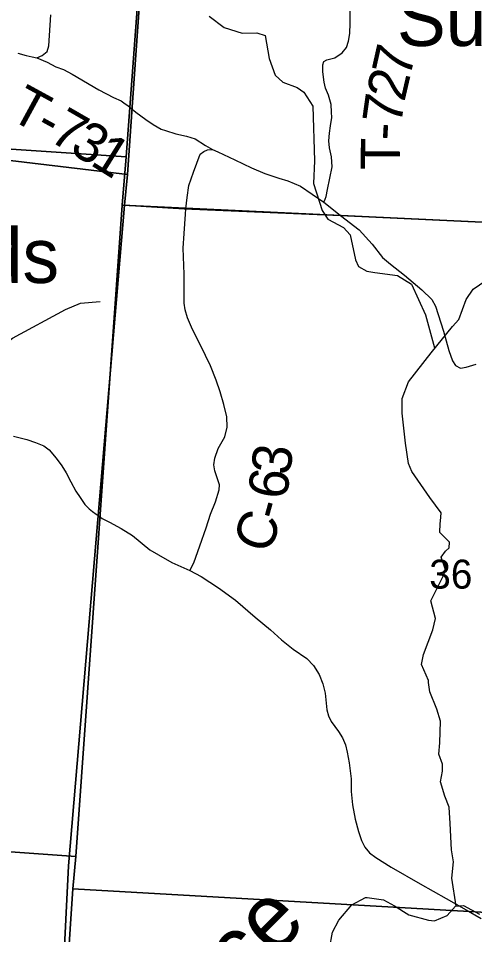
# Model space of a CAD drawing. Extents: x 1878108 to 2183446, y 146837 to 508383.
# Drawn here: x 2015902 to 2019382, y 336667 to 343657 of the extents above; entities that cross this region are included whole.
import ezdxf

# ---------------------------------------------------------------- set-up
doc = ezdxf.new("R2010")
doc.units = 0
for name, color, linetype in [('GM_X_County_Road', 7, 'Continuous'), ('GM_X_County_Road_Text', 7, 'Continuous'), ('GM_X_Minor_River', 7, 'Continuous'), ('GM_X_Minor_River_Text', 7, 'Continuous'), ('GM_X_Section', 7, 'Continuous'), ('GM_X_Section_Text', 7, 'Continuous'), ('GM_X_Township', 7, 'Continuous'), ('GM_X_Township_Road', 7, 'Continuous'), ('GM_X_Township_Road_Text', 7, 'Continuous'), ('GM_X_Unincorporated_Text', 7, 'Continuous')]:
    doc.layers.add(name, color=color, linetype=linetype)

msp = doc.modelspace()

# ---------------------------------------------------------------- linework, layer by layer
at = {"layer": 'GM_X_County_Road'}
for points in [[(2015898.6, 343392.5), (2015962.6, 343374.5), (2016007.5, 343363.3), (2016044.3, 343357), (2016083.9, 343374.5), (2016120.9, 343404.8), (2016135.5, 343447.5), (2016149, 343684.4)], [(2017177, 342162.8), (2017179.9, 342203.8), (2017190.4, 342290.2), (2017202.1, 342381.1), (2017237.3, 342483.8), (2017288.1, 342620.6), (2017316.4, 342642.1), (2017344.8, 342654.8), (2017383.9, 342655.8), (2017423, 342639.1), (2017552.9, 342576.6), (2017680, 342516), (2017782.6, 342474), (2017888.2, 342437.8), (2017956.6, 342418.3), (2018053.8, 342376.3), (2018231.1, 342253.6), (2018355.4, 342154.9)], [(2017210.9, 339445.2), (2017239.2, 339503.9), (2017285.2, 339632), (2017334, 339769.8), (2017368.2, 339874.3), (2017406.4, 339968.2), (2017433.7, 340059.1), (2017435.7, 340098.1), (2017423.9, 340136.3), (2017399.5, 340205.7), (2017393.6, 340250.6), (2017400.5, 340302.4), (2017426.9, 340375.7), (2017475.7, 340465.6), (2017493.3, 340537.9), (2017492.4, 340616.1), (2017469.9, 340711.9), (2017440.6, 340807.7), (2017410.3, 340895.6), (2017366.3, 341005.1), (2017329.1, 341086.2), (2017287.1, 341173.2), (2017231.4, 341283.6), (2017191.3, 341373.5), (2017174.7, 341432.2), (2017165.9, 341484), (2017166.9, 341596.4), (2017165.9, 341704.8), (2017158.1, 341903.2), (2017166.9, 342014.6), (2017177, 342162.8)], [(2018355.4, 342154.9), (2018357.7, 342153.1), (2018501, 342044.8), (2018600.4, 341934.3), (2018678, 341832), (2018739.2, 341782.6), (2018847.8, 341698), (2018979, 341585.1), (2019054.2, 341512.2), (2019083.6, 341461.7), (2019144.7, 341271.2), (2019185.9, 341123.1), (2019211.7, 341044.4), (2019235.2, 341009.1), (2019272.9, 340987.9), (2019316.3, 340995), (2019393.9, 341018.5)], [(2015866, 340470.3), (2015968, 340443.2), (2016032.5, 340421.3), (2016095.7, 340395.5), (2016138.3, 340365.8), (2016189.9, 340301.3), (2016235.1, 340243.2), (2016267.3, 340190.3), (2016302.2, 340120.6), (2016339.6, 340049.7), (2016374.4, 340000.6), (2016410.5, 339947.7), (2016442.8, 339915.5), (2016467.3, 339894.8), (2016496.6, 339874.8)], [(2016496.6, 339874.8), (2016510.3, 339865.4), (2016542.2, 339841.9), (2016596.4, 339812.3), (2016686.7, 339765.8), (2016771.8, 339711.6), (2016906, 339603.2), (2016970.5, 339563.2), (2017073.8, 339506.5), (2017210.9, 339445.2)], [(2017210.9, 339445.2), (2017295.7, 339399.4), (2017427.3, 339311.6), (2017558.9, 339217.4), (2017708.6, 339089.7), (2017824.7, 338991.6), (2017909.9, 338916.8), (2017998.9, 338845.8), (2018100.9, 338772.3), (2018153.8, 338720.7), (2018196.3, 338652.3), (2018223.4, 338580), (2018241.5, 338509), (2018255.7, 338382.6), (2018266, 338336.1), (2018286.7, 338293.6), (2018343.4, 338216.1), (2018374.4, 338167.1), (2018396.3, 338115.5), (2018410.5, 338060), (2018424.7, 337977.4), (2018438.9, 337856.1), (2018438.9, 337759.4), (2018450.5, 337656.1), (2018469.9, 337549), (2018497, 337453.6), (2018517.6, 337383.9), (2018543.4, 337333.6), (2018580.9, 337289.7), (2018628.6, 337254.9), (2018744.7, 337181.3), (2018966.7, 337053.6), (2019164.1, 336942.6), (2019317.6, 336854.9), (2019432.5, 336789.1)]]:
    msp.add_lwpolyline(points, dxfattribs=at)
at = {"layer": 'GM_X_Minor_River'}
for points in [[(2017358.5, 343674.5), (2017472.9, 343588.5), (2017609.2, 343544.7), (2017721.3, 343547), (2017783.5, 343527.1), (2017815.9, 343350.6), (2017860.2, 343222.4), (2017918.4, 343170.4), (2018028.7, 343128.5), (2018078.8, 343094.5), (2018147.2, 342986.4), (2018160.1, 342571.2), (2018152.5, 342396.7), (2018219, 342192.3), (2018263.3, 342126.2), (2018381.6, 342060.3), (2018431.8, 342006.2), (2018472.3, 341813.8), (2018496.4, 341763.7), (2018560.6, 341727.7), (2018620.7, 341717.9), (2018793, 341694.2), (2018901.3, 341630.3), (2019006, 341395.9), (2019076.4, 341142.8)], [(2019241.4, 336884.6), (2019208.2, 337096.7), (2019220.1, 337223), (2019206, 337313.3), (2019195.9, 337515.8), (2019187.8, 337640.2), (2019153.7, 337724.3), (2019121.6, 337832.6), (2019135.5, 337912.8), (2019135.5, 337967), (2019109.4, 338043.2), (2019115.4, 338129.4), (2019121.2, 338295.9), (2019093.2, 338386.1), (2019041.1, 338520.4), (2019031, 338590.6), (2019029, 338606.6), (2018976.9, 338726.8), (2018992.8, 338805.1), (2019062.6, 338991.7), (2019082.6, 339078), (2019046.5, 339214.3), (2019142.3, 339401), (2019158.2, 339451.1), (2019126.1, 339547.4), (2019160.1, 339593.5), (2019186.1, 339617.7), (2019190, 339661.8), (2019116, 339733.9), (2019117.9, 339804), (2019121.9, 339820.1), (2019125.9, 339884.3), (2019039.8, 340000.5), (2018903.7, 340200.8), (2018877.6, 340260.9), (2018853.5, 340415.3), (2018829.3, 340645.9), (2018829.2, 340758.2), (2018877.1, 340884.6), (2019050.8, 341105.5), (2019212.6, 341306.3), (2019260.5, 341360.5), (2019316.4, 341511), (2019370.3, 341591.3), (2019570.1, 341728.1)], [(2015247.7, 340749.3), (2015361.5, 340904.9), (2015427.4, 340955.1), (2015539.3, 340991.3), (2015659, 341067.6), (2015858.7, 341216.1), (2016262, 341435.1), (2016375.8, 341483.4), (2016525.6, 341495.7)], [(2018275.1, 336557.6), (2018297, 336686), (2018344.9, 336778.3), (2018444.7, 336894.8), (2018548.6, 336951.2), (2018562.6, 336951.2), (2018686.6, 336931.3), (2018770.6, 336887.4), (2018880.6, 336817.3), (2019030.6, 336777.5), (2019076.5, 336771.5), (2019172.5, 336811.8), (2019234.4, 336884.1), (2019296.4, 336888.2), (2019418.4, 336822.2)]]:
    msp.add_lwpolyline(points, dxfattribs=at)
at = {"layer": 'GM_X_Section'}
for points in [[(2017121.1, 347933.9), (2017107.5, 347769.8), (2016724.2, 342600), (2011392.3, 342956.8), (2011214.3, 342968.4), (2011587.2, 348298.2)], [(2022491.3, 347433.1), (2022076.7, 341977.1), (2016695, 342231.8), (2016724.2, 342600), (2017107.5, 347769.8)], [(2011392.3, 342956.8), (2016724.2, 342600), (2016695, 342231.8), (2016339.4, 337264), (2011013.4, 337644.9)], [(2016695, 342231.8), (2022076.7, 341977.1), (2021741.7, 336707.3), (2016317.9, 337015.9), (2016339.4, 337264)], [(2016339.4, 337264), (2016317.9, 337015.9), (2015982.4, 331960.2), (2010634.5, 332291), (2011013.4, 337644.9)], [(2021741.7, 336707.3), (2021372.8, 331397.4), (2015958.9, 331706.1), (2015982.4, 331960.2), (2016317.9, 337015.9)]]:
    msp.add_lwpolyline(points, close=True, dxfattribs=at)
at = {"layer": 'GM_X_Township'}
for points in [[(2022085.4, 341976.5), (2018357.7, 342153.1), (2017167.6, 342204.4), (2016711.2, 342233), (2016735.7, 342465.3), (2016771.3, 342980.5), (2016876.3, 344500.5), (2017298, 350114.1), (2017363.4, 350984.7), (2017639.3, 354834.1), (2017696.9, 355615), (2017915.9, 358580.9), (2018284.3, 364566.1), (2018295.1, 364714.1), (2018544, 369044.3), (2019393.9, 369074.7)], [(2017298, 350114.1), (2016876.3, 344500.5), (2016771.3, 342980.5), (2016735.7, 342465.3), (2014090.7, 342780.8), (2012240.2, 342898.1), (2008693, 343157.7), (2004354.1, 343457.5), (2003141.6, 343548.2), (2000896.9, 343716.1), (1999693.4, 343807.9), (1997660.6, 343962.9), (1995715.1, 344111.2), (1994970.8, 344177.4), (1990310.6, 344542.4), (1989690.7, 344598.5), (1988327.1, 344706.4), (1984472.4, 345011.3), (1984423, 345015.2), (1984436.4, 345172.5), (1984507.3, 345999.8), (1984847.2, 350030.1)], [(2004354.1, 343457.5), (2008693, 343157.7), (2012240.2, 342898.1), (2014090.7, 342780.8), (2016735.7, 342465.3), (2016711.2, 342233), (2016507.5, 339833.1), (2016283.5, 337192.7), (2016112.8, 333710.8), (2015936.6, 331921.1), (2015741, 328246.1), (2015410.7, 323562.4), (2015321.9, 322207.3), (2015298.1, 321725.4), (2015269.1, 321317.3), (2015253.9, 321234.4), (2015228.5, 320852.6), (2015188.5, 320381.6), (2015103.2, 319163.9), (2014740.5, 313957.9), (2014657.9, 312772.2), (2014499.4, 310496.8)], [(2014499.4, 310496.8), (2014657.9, 312772.2), (2014740.5, 313957.9), (2015103.2, 319163.9), (2015188.5, 320381.6), (2015228.5, 320852.6), (2015253.9, 321234.4), (2015269.1, 321317.3), (2015298.1, 321725.4), (2015321.9, 322207.3), (2015410.7, 323562.4), (2015741, 328246.1), (2015936.6, 331921.1), (2016112.8, 333710.8), (2016283.5, 337192.7), (2016507.5, 339833.1), (2016711.2, 342233), (2017167.6, 342204.4), (2018357.7, 342153.1), (2022085.4, 341976.5)]]:
    msp.add_lwpolyline(points, dxfattribs=at)
at = {"layer": 'GM_X_Township_Road'}
for points in [[(2018231.1, 342253.6), (2018240.7, 342277.5), (2018249, 342298.7), (2018260.7, 342350.4), (2018294.8, 342523.2), (2018290.1, 342600.8), (2018274.8, 342670.1), (2018270.1, 342723), (2018274.8, 342780.6), (2018283, 342837.1), (2018292.4, 342899.4), (2018291.3, 342941.7), (2018286.6, 342999.3), (2018267.8, 343069.8), (2018244.3, 343123.9), (2018233.7, 343169.7), (2018223.1, 343248.5), (2018222.8, 343302.7), (2018232.5, 343328.4), (2018254.8, 343340.2), (2018314.8, 343355.5), (2018371.2, 343394.3), (2018405.3, 343435.4), (2018420.6, 343483.6), (2018430, 343542.4), (2018433.5, 343621.2), (2018432.3, 343741.1)], [(2016044.3, 343357), (2016122.1, 343322.8), (2016189.4, 343286.9), (2016245.5, 343266.7), (2016312.9, 343230.8), (2016515, 343111.8), (2016628.4, 343053.4), (2016685.6, 343027.6), (2016717.8, 343004.8)], [(2016717.8, 343004.8), (2016735.9, 342992), (2016770.1, 342963.6), (2016798.5, 342940.2), (2016873.7, 342886.4), (2016931.4, 342848.3), (2016992, 342812.1), (2017023.2, 342800.4), (2017104.4, 342776.9), (2017185.5, 342759.4), (2017250, 342737.9), (2017330.1, 342686.1), (2017383.9, 342655.8)]]:
    msp.add_lwpolyline(points, dxfattribs=at)

# ---------------------------------------------------------------- texts
at = {"layer": 'GM_X_County_Road_Text'}
for s, rotation, p in [('3', 82.8041, (2017972.4, 340165.2)), ('6', 82.37559, (2017947.5, 339979.6)), ('-', 74.40004, (2017905.3, 339816.3)), ('C', 69.88384, (2017812.6, 339560.3))]:
    msp.add_text(s, height=300, rotation=rotation, dxfattribs=at).set_placement(p)
at = {"layer": 'GM_X_Minor_River_Text'}
msp.add_text('Trace', height=499.97, rotation=44.99806, dxfattribs=at).set_placement((2016903.4, 335543.1))
at = {"layer": 'GM_X_Section_Text'}
msp.add_text('36', height=221, rotation=0.00001, dxfattribs=at).set_placement((2019035.6, 339306.6))
at = {"layer": 'GM_X_Township_Road_Text'}
for s, rotation, p in [('7', 77.28963, (2018887, 343195.1)), ('2', 76.93439, (2018844.7, 343013.2)), ('T', 331.37997, (2015820.9, 342897)), ('7', 81.97514, (2018820.2, 342837)), ('7', 330.06084, (2016124, 342730.6)), ('-', 330.97649, (2016017.4, 342789.8)), ('3', 328.99252, (2016282.9, 342639.2)), ('-', 86.80587, (2018814, 342720.7)), ('1', 328.13307, (2016440.3, 342544.6)), ('T', 89.63571, (2018812.7, 342500.2))]:
    msp.add_text(s, height=300, rotation=rotation, dxfattribs=at).set_placement(p)
at = {"layer": 'GM_X_Unincorporated_Text'}
for s, p in [('Summitt', (2018789.2, 343446.5)), ('Woods', (2014477.2, 341638))]:
    msp.add_text(s, height=417, rotation=0.00001, dxfattribs=at).set_placement(p)

doc.saveas('drawing.dxf')
